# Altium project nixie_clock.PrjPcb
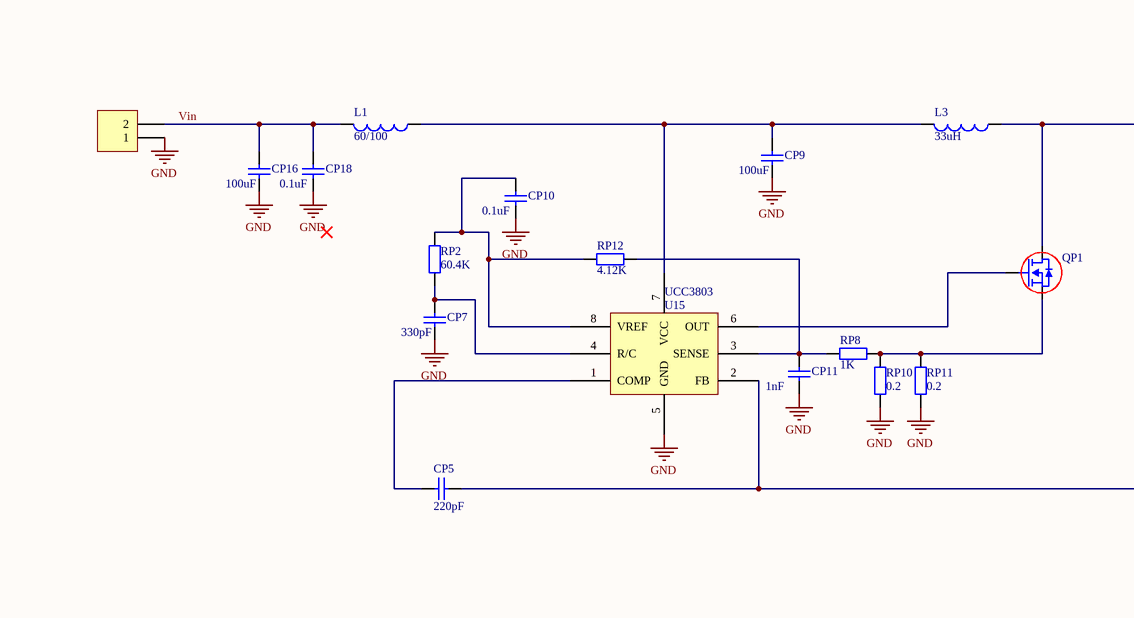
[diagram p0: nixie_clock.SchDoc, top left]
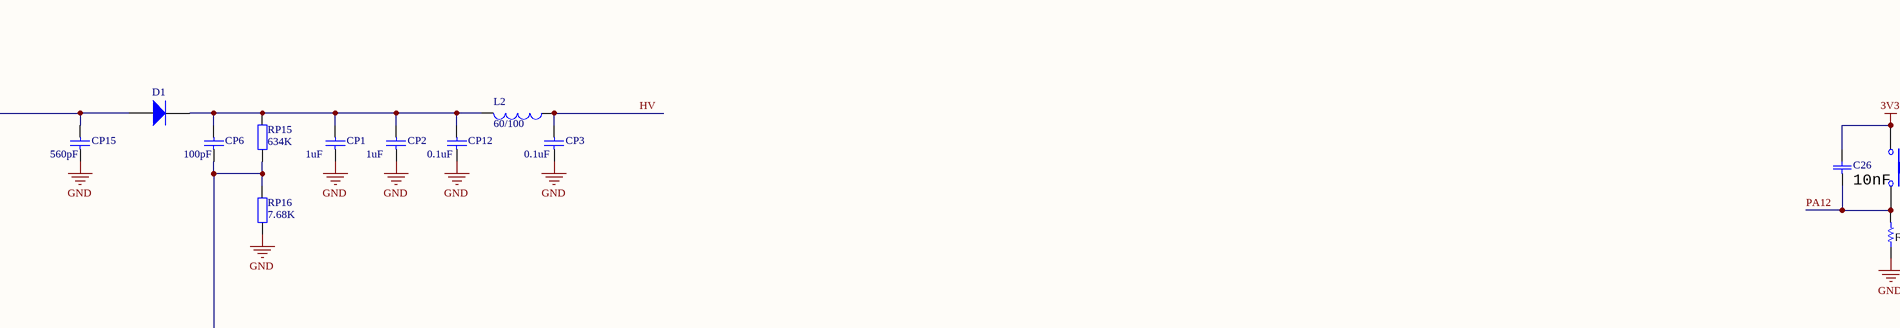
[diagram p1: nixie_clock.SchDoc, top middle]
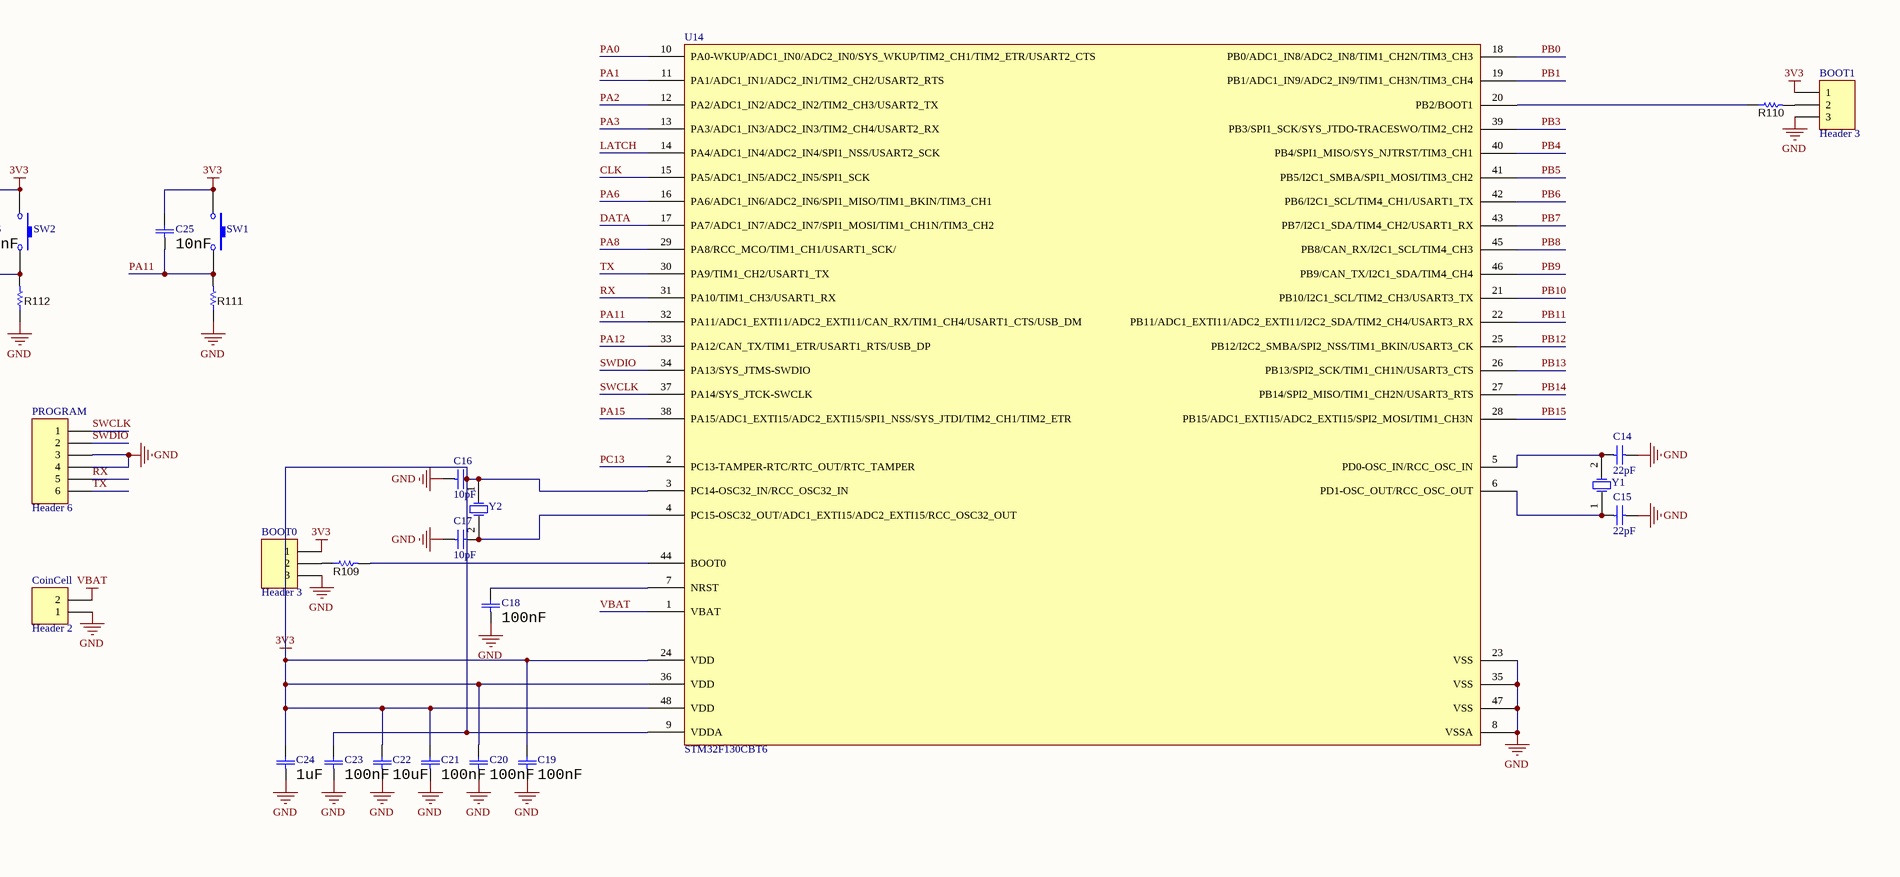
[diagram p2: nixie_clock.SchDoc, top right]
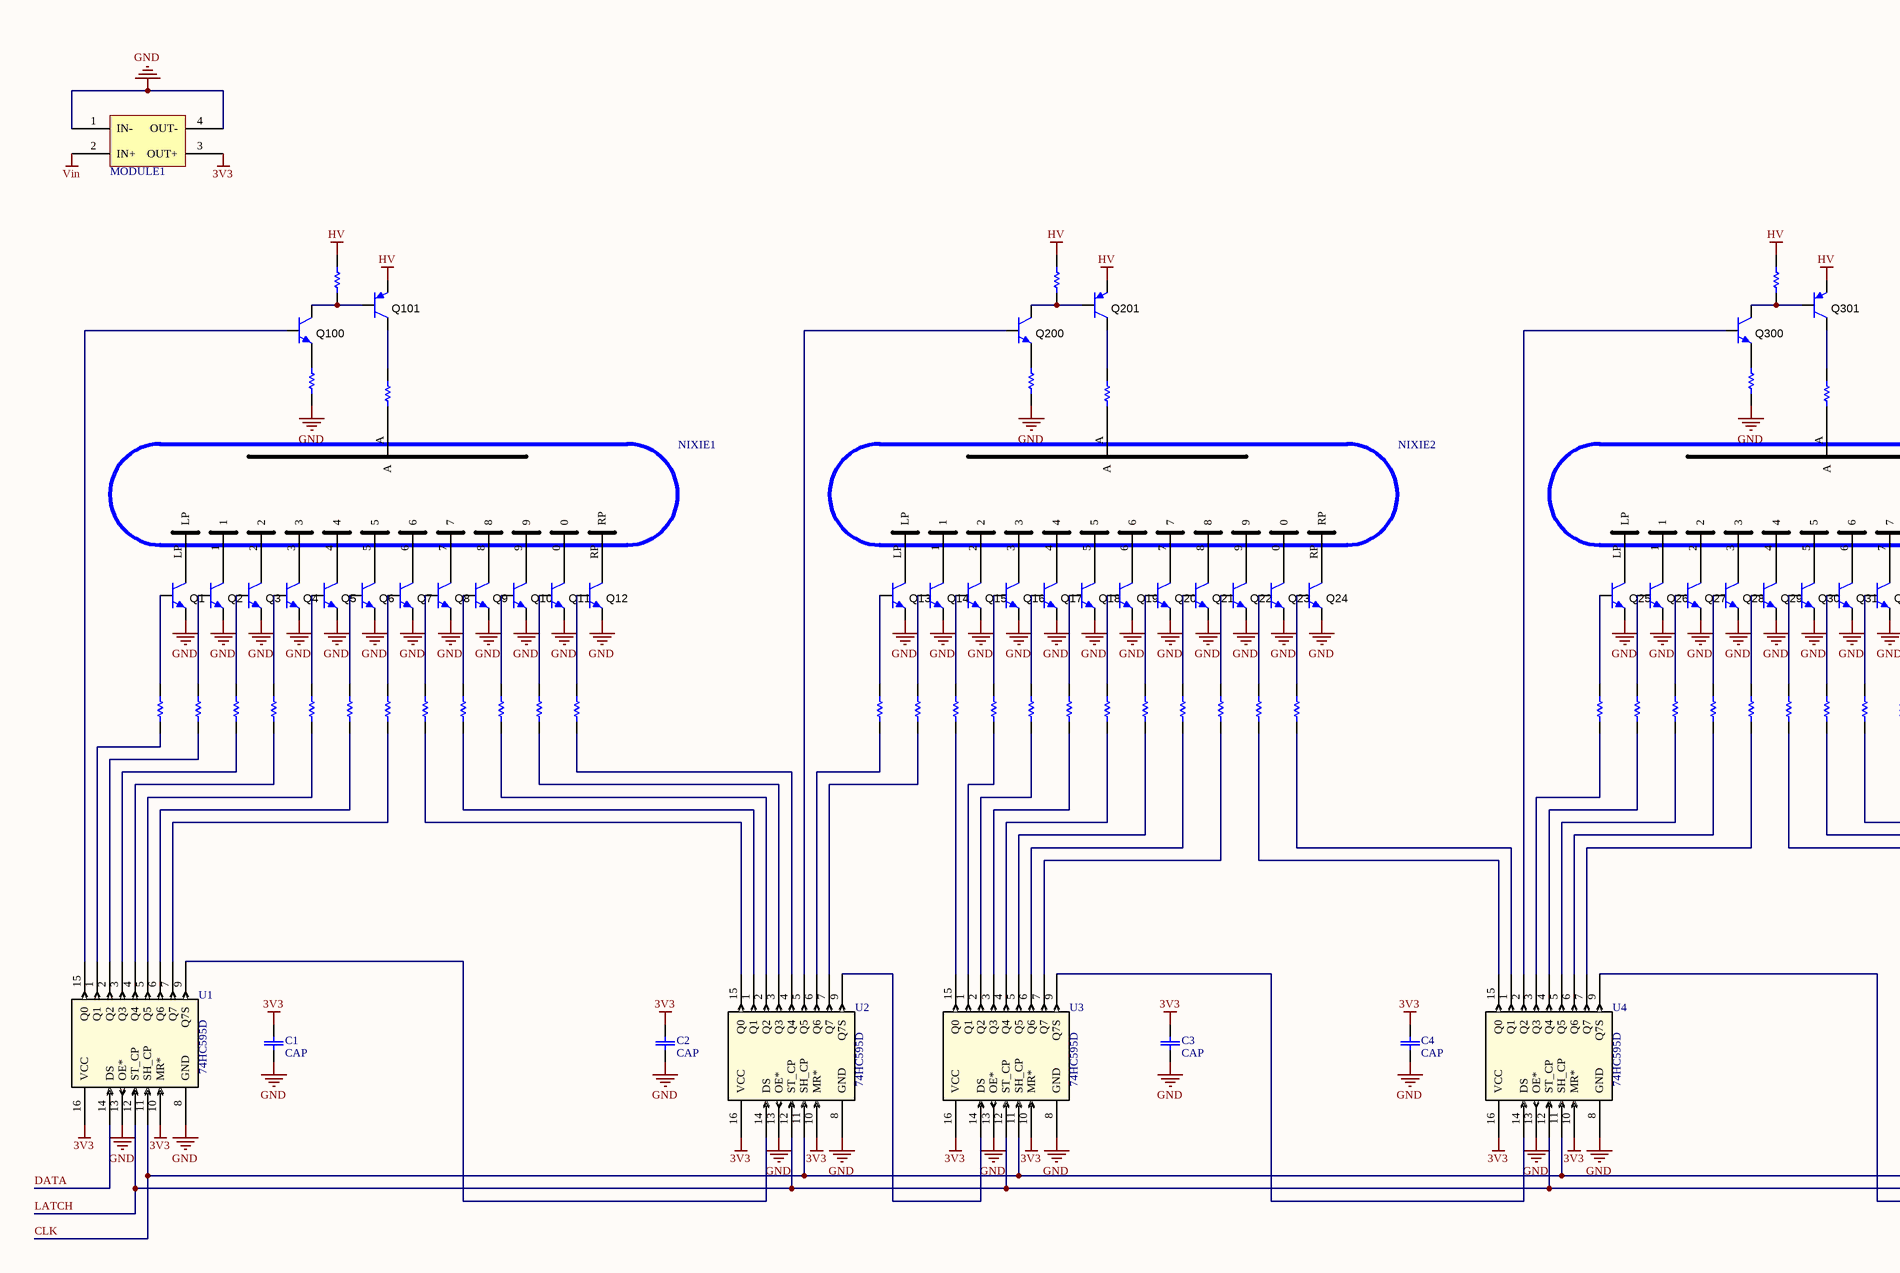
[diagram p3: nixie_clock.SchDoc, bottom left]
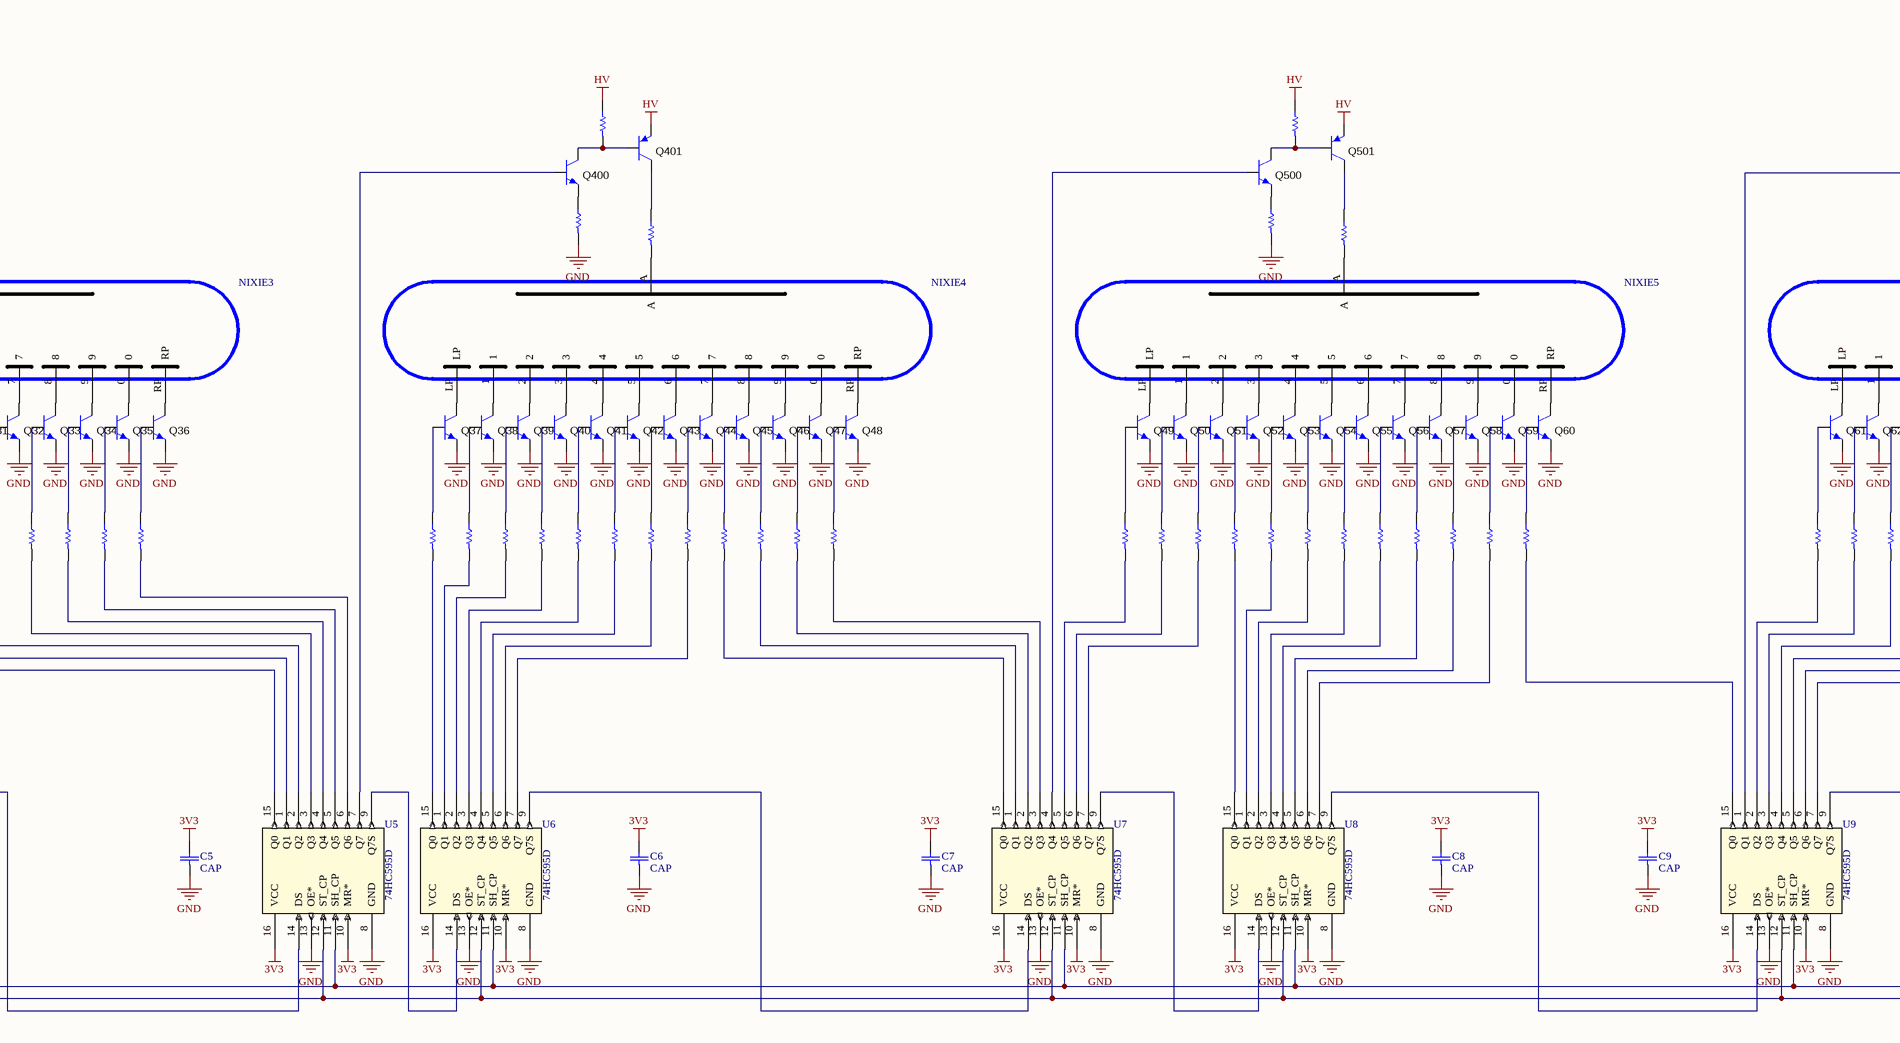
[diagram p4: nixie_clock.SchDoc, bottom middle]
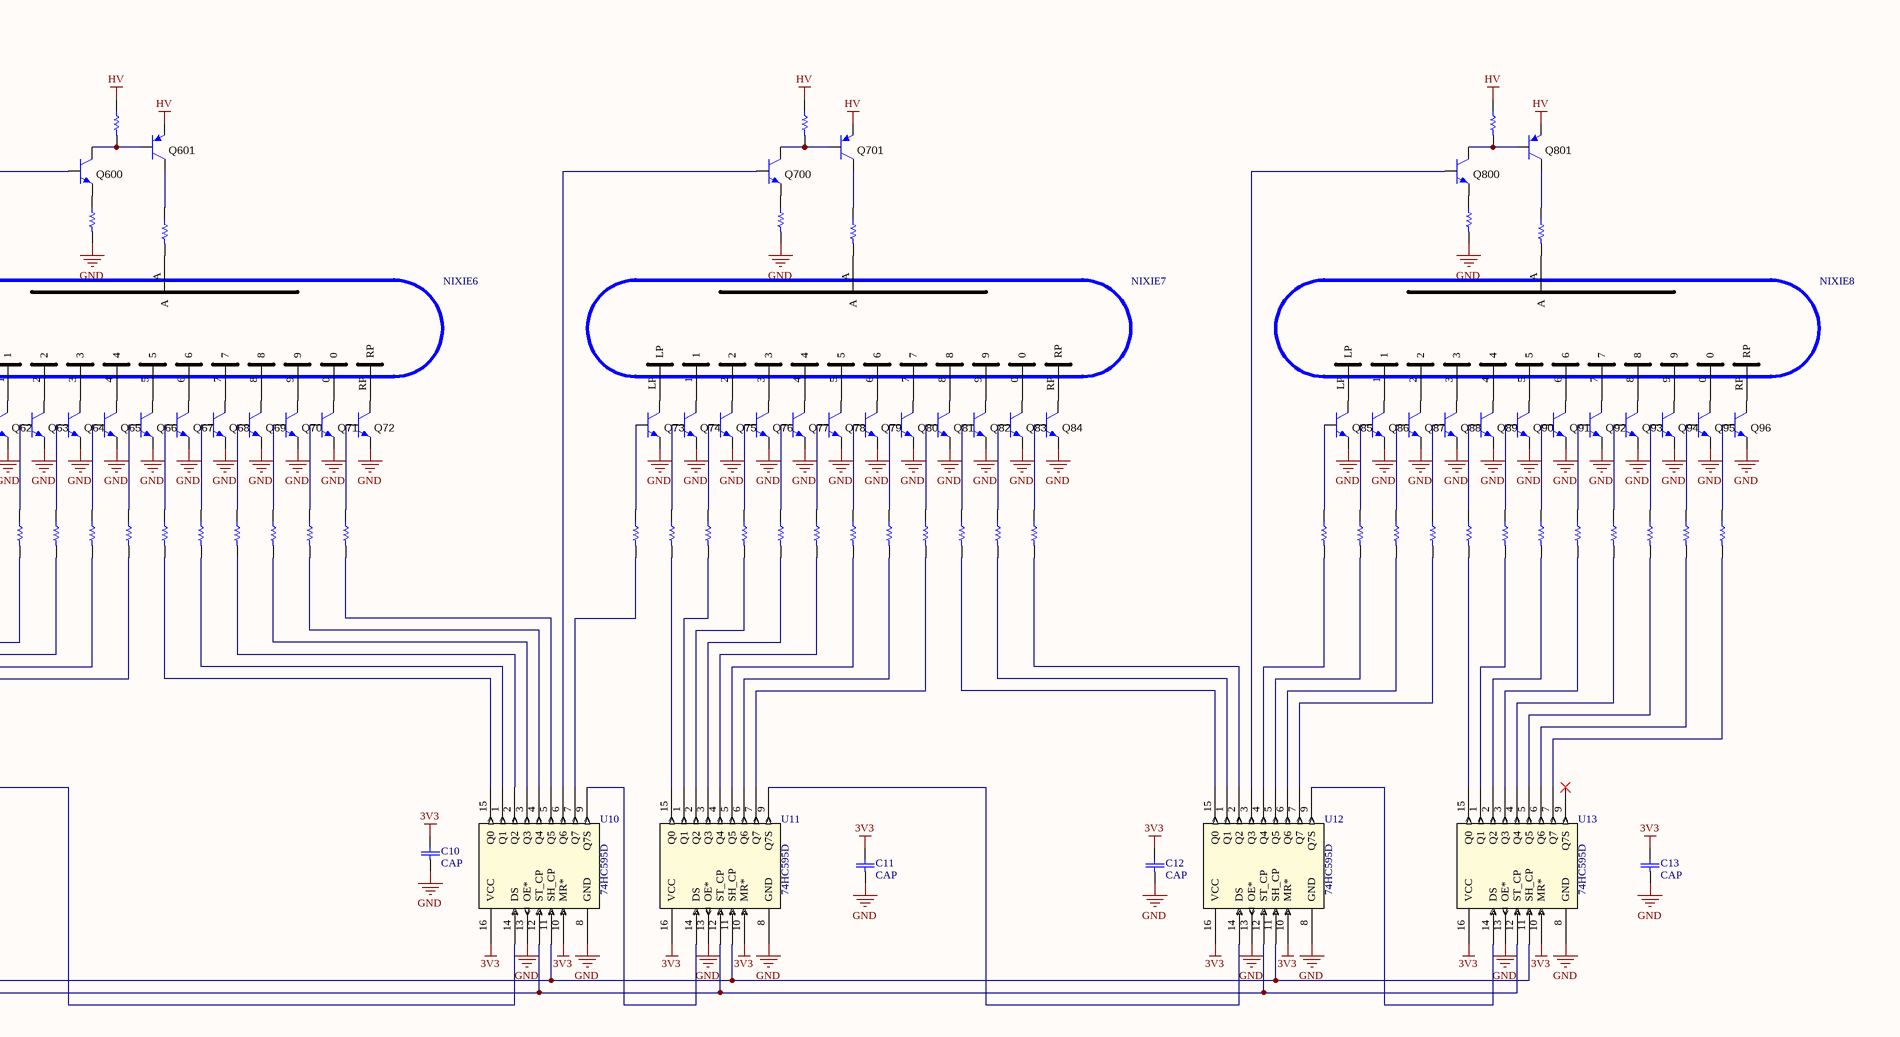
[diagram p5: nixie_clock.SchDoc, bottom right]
1 sheet, 320 parts. Net scope: global (net labels, ports and power ports of the same name join across sheets).
Board file: nixie_clock.PcbDoc

## Sheet nixie_clock.SchDoc
size 1270 x 635 mm; PageSetup: Record=PageOptions¦CenterHorizontal=True¦CenterVertical=True¦PrintScale=0.92¦XCorrection=1.00¦YCorrection=1.00¦PrintKind=0¦BorderSize=5000000¦LeftOffset=0¦BottomOffset=0¦Orientation=2¦PaperLength=11890¦PaperWidth=8410¦Scale=100¦PaperSource=7¦PrintQuality=600¦MediaType=1¦DitherType=10¦PrintScaleMode=1¦PaperKind=A0¦PaperIndex=119

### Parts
BOOT0  Header 3  [SMDJ]
BOOT1  Header 3  [smdj]
C1  CAP  [SMD[1206]]
C2  CAP  [SMD[1206]]
C3  CAP  [SMD[1206]]
C4  CAP  [SMD[1206]]
C5  CAP  [SMD[1206]]
C6  CAP  [SMD[1206]]
C7  CAP  [SMD[1206]]
C8  CAP  [SMD[1206]]
C9  CAP  [SMD[1206]]
C10  CAP  [SMD[1206]]
C11  CAP  [SMD[1206]]
C12  CAP  [SMD[1206]]
C13  CAP  [SMD[1206]]
C14  value 22pF  [SMD[1206]]  (hidden comment: Cap)
C15  value 22pF  [SMD[1206]]  (hidden comment: Cap)
C16  value 10pF  [SMD[0805]]  (hidden comment: Cap)
C17  value 10pF  [SMD[0805]]  (hidden comment: Cap)
C18  value 100nF  [SMD[1206]]  (hidden comment: CAP)
C19  value 100nF  [SMD[1206]]  (hidden comment: CAP)
C20  value 100nF  [SMD[1206]]  (hidden comment: CAP)
C21  value 100nF  [SMD[1206]]  (hidden comment: CAP)
C22  value 10uF  [SMD[1206]]  (hidden comment: CAP)
C23  value 100nF  [SMD[1206]]  (hidden comment: CAP)
C24  value 1uF  [SMD[1206]]  (hidden comment: CAP)
C25  value 10nF  [SMD[1206]]  (hidden comment: CAP)
C26  value 10nF  [SMD[1206]]  (hidden comment: CAP)
CoinCell  Header 2  [CoinCell[CR2032]]
CP1  value 1uF  [MKT27X10]  (hidden comment: Cap Semi)
CP2  value 1uF  [MKT27X10]  (hidden comment: Cap Semi)
CP3  value 0.1uF  [MKT18X6]  (hidden comment: Cap Semi)
CP5  value 220pF  [SMD[1206]]  (hidden comment: Cap Semi)
CP6  value 100pF  [CAP[SEC]]  (hidden comment: Cap Semi)
CP7  value 330pF  [SMD[1206]]  (hidden comment: Cap Semi)
CP9  value 100uF  [SMDCAP[D]]  (hidden comment: Cap Semi)
CP10  value 0.1uF  [SMDCAP[A]]  (hidden comment: Cap Semi)
CP11  value 1nF  [SMD[1206]]  (hidden comment: Cap Semi)
CP12  value 0.1uF  [MKT18X6]  (hidden comment: Cap Semi)
CP15  value 560pF  [CAP[SEC]]  (hidden comment: Cap Semi)
CP16  value 100uF  [SMDCAP[D]]  (hidden comment: Cap Semi)
CP18  value 0.1uF  [SMDCAP[A]]  (hidden comment: Cap Semi)
D1  Diode  [TO-220H-2PIN]  (value not drawn)
L1  value 60/100  [SMD[1206]]  (hidden comment: Inductor)
L2  value 60/100  [SMD[1206]]  (hidden comment: Inductor)
L3  value 33uH  [POWERINDUCTOR]  (hidden comment: Inductor)
MODULE1  TINY_STEPDOWN  [TINY_STEPDOWN]  (value not drawn)
NIXIE1  IN14_NIXIE_TUBE  [IN14_NIXIE_TUBE]  (value not drawn)
NIXIE2  IN14_NIXIE_TUBE  [IN14_NIXIE_TUBE]  (value not drawn)
NIXIE3  IN14_NIXIE_TUBE  [IN14_NIXIE_TUBE]  (value not drawn)
NIXIE4  IN14_NIXIE_TUBE  [IN14_NIXIE_TUBE]  (value not drawn)
NIXIE5  IN14_NIXIE_TUBE  [IN14_NIXIE_TUBE]  (value not drawn)
NIXIE6  IN14_NIXIE_TUBE  [IN14_NIXIE_TUBE]  (value not drawn)
NIXIE7  IN14_NIXIE_TUBE  [IN14_NIXIE_TUBE]  (value not drawn)
NIXIE8  IN14_NIXIE_TUBE  [IN14_NIXIE_TUBE]  (value not drawn)
P1  Header 2  [HDR1X2]  (value not drawn)
PROGRAM  Header 6  [H1X06F]
Q1  MMBTA42  [SOT23(TO236)]  (value not drawn)
Q2  MMBTA42  [SOT23(TO236)]  (value not drawn)
Q3  MMBTA42  [SOT23(TO236)]  (value not drawn)
Q4  MMBTA42  [SOT23(TO236)]  (value not drawn)
Q5  MMBTA42  [SOT23(TO236)]  (value not drawn)
Q6  MMBTA42  [SOT23(TO236)]  (value not drawn)
Q7  MMBTA42  [SOT23(TO236)]  (value not drawn)
Q8  MMBTA42  [SOT23(TO236)]  (value not drawn)
Q9  MMBTA42  [SOT23(TO236)]  (value not drawn)
Q10  MMBTA42  [SOT23(TO236)]  (value not drawn)
Q11  MMBTA42  [SOT23(TO236)]  (value not drawn)
Q12  MMBTA42  [SOT23(TO236)]  (value not drawn)
Q13  MMBTA42  [SOT23(TO236)]  (value not drawn)
Q14  MMBTA42  [SOT23(TO236)]  (value not drawn)
Q15  MMBTA42  [SOT23(TO236)]  (value not drawn)
Q16  MMBTA42  [SOT23(TO236)]  (value not drawn)
Q17  MMBTA42  [SOT23(TO236)]  (value not drawn)
Q18  MMBTA42  [SOT23(TO236)]  (value not drawn)
Q19  MMBTA42  [SOT23(TO236)]  (value not drawn)
Q20  MMBTA42  [SOT23(TO236)]  (value not drawn)
Q21  MMBTA42  [SOT23(TO236)]  (value not drawn)
Q22  MMBTA42  [SOT23(TO236)]  (value not drawn)
Q23  MMBTA42  [SOT23(TO236)]  (value not drawn)
Q24  MMBTA42  [SOT23(TO236)]  (value not drawn)
Q25  MMBTA42  [SOT23(TO236)]  (value not drawn)
Q26  MMBTA42  [SOT23(TO236)]  (value not drawn)
Q27  MMBTA42  [SOT23(TO236)]  (value not drawn)
Q28  MMBTA42  [SOT23(TO236)]  (value not drawn)
Q29  MMBTA42  [SOT23(TO236)]  (value not drawn)
Q30  MMBTA42  [SOT23(TO236)]  (value not drawn)
Q31  MMBTA42  [SOT23(TO236)]  (value not drawn)
Q32  MMBTA42  [SOT23(TO236)]  (value not drawn)
Q33  MMBTA42  [SOT23(TO236)]  (value not drawn)
Q34  MMBTA42  [SOT23(TO236)]  (value not drawn)
Q35  MMBTA42  [SOT23(TO236)]  (value not drawn)
Q36  MMBTA42  [SOT23(TO236)]  (value not drawn)
Q37  MMBTA42  [SOT23(TO236)]  (value not drawn)
Q38  MMBTA42  [SOT23(TO236)]  (value not drawn)
Q39  MMBTA42  [SOT23(TO236)]  (value not drawn)
Q40  MMBTA42  [SOT23(TO236)]  (value not drawn)
Q41  MMBTA42  [SOT23(TO236)]  (value not drawn)
Q42  MMBTA42  [SOT23(TO236)]  (value not drawn)
Q43  MMBTA42  [SOT23(TO236)]  (value not drawn)
Q44  MMBTA42  [SOT23(TO236)]  (value not drawn)
Q45  MMBTA42  [SOT23(TO236)]  (value not drawn)
Q46  MMBTA42  [SOT23(TO236)]  (value not drawn)
Q47  MMBTA42  [SOT23(TO236)]  (value not drawn)
Q48  MMBTA42  [SOT23(TO236)]  (value not drawn)
Q49  MMBTA42  [SOT23(TO236)]  (value not drawn)
Q50  MMBTA42  [SOT23(TO236)]  (value not drawn)
Q51  MMBTA42  [SOT23(TO236)]  (value not drawn)
Q52  MMBTA42  [SOT23(TO236)]  (value not drawn)
Q53  MMBTA42  [SOT23(TO236)]  (value not drawn)
Q54  MMBTA42  [SOT23(TO236)]  (value not drawn)
Q55  MMBTA42  [SOT23(TO236)]  (value not drawn)
Q56  MMBTA42  [SOT23(TO236)]  (value not drawn)
Q57  MMBTA42  [SOT23(TO236)]  (value not drawn)
Q58  MMBTA42  [SOT23(TO236)]  (value not drawn)
Q59  MMBTA42  [SOT23(TO236)]  (value not drawn)
Q60  MMBTA42  [SOT23(TO236)]  (value not drawn)
Q61  MMBTA42  [SOT23(TO236)]  (value not drawn)
Q62  MMBTA42  [SOT23(TO236)]  (value not drawn)
Q63  MMBTA42  [SOT23(TO236)]  (value not drawn)
Q64  MMBTA42  [SOT23(TO236)]  (value not drawn)
Q65  MMBTA42  [SOT23(TO236)]  (value not drawn)
Q66  MMBTA42  [SOT23(TO236)]  (value not drawn)
Q67  MMBTA42  [SOT23(TO236)]  (value not drawn)
Q68  MMBTA42  [SOT23(TO236)]  (value not drawn)
Q69  MMBTA42  [SOT23(TO236)]  (value not drawn)
Q70  MMBTA42  [SOT23(TO236)]  (value not drawn)
Q71  MMBTA42  [SOT23(TO236)]  (value not drawn)
Q72  MMBTA42  [SOT23(TO236)]  (value not drawn)
Q73  MMBTA42  [SOT23(TO236)]  (value not drawn)
Q74  MMBTA42  [SOT23(TO236)]  (value not drawn)
Q75  MMBTA42  [SOT23(TO236)]  (value not drawn)
Q76  MMBTA42  [SOT23(TO236)]  (value not drawn)
Q77  MMBTA42  [SOT23(TO236)]  (value not drawn)
Q78  MMBTA42  [SOT23(TO236)]  (value not drawn)
Q79  MMBTA42  [SOT23(TO236)]  (value not drawn)
Q80  MMBTA42  [SOT23(TO236)]  (value not drawn)
Q81  MMBTA42  [SOT23(TO236)]  (value not drawn)
Q82  MMBTA42  [SOT23(TO236)]  (value not drawn)
Q83  MMBTA42  [SOT23(TO236)]  (value not drawn)
Q84  MMBTA42  [SOT23(TO236)]  (value not drawn)
Q85  MMBTA42  [SOT23(TO236)]  (value not drawn)
Q86  MMBTA42  [SOT23(TO236)]  (value not drawn)
Q87  MMBTA42  [SOT23(TO236)]  (value not drawn)
Q88  MMBTA42  [SOT23(TO236)]  (value not drawn)
Q89  MMBTA42  [SOT23(TO236)]  (value not drawn)
Q90  MMBTA42  [SOT23(TO236)]  (value not drawn)
Q91  MMBTA42  [SOT23(TO236)]  (value not drawn)
Q92  MMBTA42  [SOT23(TO236)]  (value not drawn)
Q93  MMBTA42  [SOT23(TO236)]  (value not drawn)
Q94  MMBTA42  [SOT23(TO236)]  (value not drawn)
Q95  MMBTA42  [SOT23(TO236)]  (value not drawn)
Q96  MMBTA42  [SOT23(TO236)]  (value not drawn)
Q100  MMBTA42  [SOT23(TO236)]  (value not drawn)
Q101  MMBTA92  [SOT23(TO236)]  (value not drawn)
Q200  MMBTA42  [SOT23(TO236)]  (value not drawn)
Q201  MMBTA92  [SOT23(TO236)]  (value not drawn)
Q300  MMBTA42  [SOT23(TO236)]  (value not drawn)
Q301  MMBTA92  [SOT23(TO236)]  (value not drawn)
Q400  MMBTA42  [SOT23(TO236)]  (value not drawn)
Q401  MMBTA92  [SOT23(TO236)]  (value not drawn)
Q500  MMBTA42  [SOT23(TO236)]  (value not drawn)
Q501  MMBTA92  [SOT23(TO236)]  (value not drawn)
Q600  MMBTA42  [SOT23(TO236)]  (value not drawn)
Q601  MMBTA92  [SOT23(TO236)]  (value not drawn)
Q700  MMBTA42  [SOT23(TO236)]  (value not drawn)
Q701  MMBTA92  [SOT23(TO236)]  (value not drawn)
Q800  MMBTA42  [SOT23(TO236)]  (value not drawn)
Q801  MMBTA92  [SOT23(TO236)]  (value not drawn)
QP1  IRFB4229  [TO-220H]  (value not drawn)
R1  RES  [SMD[1206]]  (value not drawn)
R2  RES  [SMD[1206]]  (value not drawn)
R3  RES  [SMD[1206]]  (value not drawn)
R4  RES  [SMD[1206]]  (value not drawn)
R5  RES  [SMD[1206]]  (value not drawn)
R6  RES  [SMD[1206]]  (value not drawn)
R7  RES  [SMD[1206]]  (value not drawn)
R8  RES  [SMD[1206]]  (value not drawn)
R9  RES  [SMD[1206]]  (value not drawn)
R10  RES  [SMD[1206]]  (value not drawn)
R11  RES  [SMD[1206]]  (value not drawn)
R12  RES  [SMD[1206]]  (value not drawn)
R13  RES  [SMD[1206]]  (value not drawn)
R14  RES  [SMD[1206]]  (value not drawn)
R15  RES  [SMD[1206]]  (value not drawn)
R16  RES  [SMD[1206]]  (value not drawn)
R17  RES  [SMD[1206]]  (value not drawn)
R18  RES  [SMD[1206]]  (value not drawn)
R19  RES  [SMD[1206]]  (value not drawn)
R20  RES  [SMD[1206]]  (value not drawn)
R21  RES  [SMD[1206]]  (value not drawn)
R22  RES  [SMD[1206]]  (value not drawn)
R23  RES  [SMD[1206]]  (value not drawn)
R24  RES  [SMD[1206]]  (value not drawn)
R25  RES  [SMD[1206]]  (value not drawn)
R26  RES  [SMD[1206]]  (value not drawn)
R27  RES  [SMD[1206]]  (value not drawn)
R28  RES  [SMD[1206]]  (value not drawn)
R29  RES  [SMD[1206]]  (value not drawn)
R30  RES  [SMD[1206]]  (value not drawn)
R31  RES  [SMD[1206]]  (value not drawn)
R32  RES  [SMD[1206]]  (value not drawn)
R33  RES  [SMD[1206]]  (value not drawn)
R34  RES  [SMD[1206]]  (value not drawn)
R35  RES  [SMD[1206]]  (value not drawn)
R36  RES  [SMD[1206]]  (value not drawn)
R37  RES  [SMD[1206]]  (value not drawn)
R38  RES  [SMD[1206]]  (value not drawn)
R39  RES  [SMD[1206]]  (value not drawn)
R40  RES  [SMD[1206]]  (value not drawn)
R41  RES  [SMD[1206]]  (value not drawn)
R42  RES  [SMD[1206]]  (value not drawn)
R43  RES  [SMD[1206]]  (value not drawn)
R44  RES  [SMD[1206]]  (value not drawn)
R45  RES  [SMD[1206]]  (value not drawn)
R46  RES  [SMD[1206]]  (value not drawn)
R47  RES  [SMD[1206]]  (value not drawn)
R48  RES  [SMD[1206]]  (value not drawn)
R49  RES  [SMD[1206]]  (value not drawn)
R50  RES  [SMD[1206]]  (value not drawn)
R51  RES  [SMD[1206]]  (value not drawn)
R52  RES  [SMD[1206]]  (value not drawn)
R53  RES  [SMD[1206]]  (value not drawn)
R54  RES  [SMD[1206]]  (value not drawn)
R55  RES  [SMD[1206]]  (value not drawn)
R56  RES  [SMD[1206]]  (value not drawn)
R57  RES  [SMD[1206]]  (value not drawn)
R58  RES  [SMD[1206]]  (value not drawn)
R59  RES  [SMD[1206]]  (value not drawn)
R60  RES  [SMD[1206]]  (value not drawn)
R61  RES  [SMD[1206]]  (value not drawn)
R62  RES  [SMD[1206]]  (value not drawn)
R63  RES  [SMD[1206]]  (value not drawn)
R64  RES  [SMD[1206]]  (value not drawn)
R65  RES  [SMD[1206]]  (value not drawn)
R66  RES  [SMD[1206]]  (value not drawn)
R67  RES  [SMD[1206]]  (value not drawn)
R68  RES  [SMD[1206]]  (value not drawn)
R69  RES  [SMD[1206]]  (value not drawn)
R70  RES  [SMD[1206]]  (value not drawn)
R71  RES  [SMD[1206]]  (value not drawn)
R72  RES  [SMD[1206]]  (value not drawn)
R73  RES  [SMD[1206]]  (value not drawn)
R74  RES  [SMD[1206]]  (value not drawn)
R75  RES  [SMD[1206]]  (value not drawn)
R76  RES  [SMD[1206]]  (value not drawn)
R77  RES  [SMD[1206]]  (value not drawn)
R78  RES  [SMD[1206]]  (value not drawn)
R79  RES  [SMD[1206]]  (value not drawn)
R80  RES  [SMD[1206]]  (value not drawn)
R81  RES  [SMD[1206]]  (value not drawn)
R82  RES  [SMD[1206]]  (value not drawn)
R83  RES  [SMD[1206]]  (value not drawn)
R84  RES  [SMD[1206]]  (value not drawn)
R85  RES  [SMD[1206]]  (value not drawn)
R86  RES  [SMD[1206]]  (value not drawn)
R87  RES  [SMD[1206]]  (value not drawn)
R88  RES  [SMD[1206]]  (value not drawn)
R89  RES  [SMD[1206]]  (value not drawn)
R90  RES  [SMD[1206]]  (value not drawn)
R91  RES  [SMD[1206]]  (value not drawn)
R92  RES  [SMD[1206]]  (value not drawn)
R93  RES  [SMD[1206]]  (value not drawn)
R94  RES  [SMD[1206]]  (value not drawn)
R95  RES  [SMD[1206]]  (value not drawn)
R96  RES  [SMD[1206]]  (value not drawn)
R100  RES  [SMD[1206]]  (value not drawn)
R101  RES  [SMD[1206]]  (value not drawn)
R102  RES  [SMD[1206]]  (value not drawn)
R109  RES  [SMD[1206]]  (value not drawn)
R110  RES  [SMD[1206]]  (value not drawn)
R111  RES  [SMD[1206]]  (value not drawn)
R112  RES  [SMD[1206]]  (value not drawn)
R200  RES  [SMD[1206]]  (value not drawn)
R201  RES  [SMD[1206]]  (value not drawn)
R202  RES  [SMD[1206]]  (value not drawn)
R300  RES  [SMD[1206]]  (value not drawn)
R301  RES  [SMD[1206]]  (value not drawn)
R302  RES  [SMD[1206]]  (value not drawn)
R400  RES  [SMD[1206]]  (value not drawn)
R401  RES  [SMD[1206]]  (value not drawn)
R402  RES  [SMD[1206]]  (value not drawn)
R500  RES  [SMD[1206]]  (value not drawn)
R501  RES  [SMD[1206]]  (value not drawn)
R502  RES  [SMD[1206]]  (value not drawn)
R600  RES  [SMD[1206]]  (value not drawn)
R601  RES  [SMD[1206]]  (value not drawn)
R602  RES  [SMD[1206]]  (value not drawn)
R700  RES  [SMD[1206]]  (value not drawn)
R701  RES  [SMD[1206]]  (value not drawn)
R702  RES  [SMD[1206]]  (value not drawn)
R800  RES  [SMD[1206]]  (value not drawn)
R801  RES  [SMD[1206]]  (value not drawn)
R802  RES  [SMD[1206]]  (value not drawn)
RP2  value 60.4K  [SMD[1206]]  (hidden comment: Res2)
RP8  value 1K  [SMD[1206]]  (hidden comment: Res2)
RP10  value 0.2  [SMD[1206]]  (hidden comment: Res2)
RP11  value 0.2  [SMD[1206]]  (hidden comment: Res2)
RP12  value 4.12K  [SMD[1206]]  (hidden comment: Res2)
RP15  value 634K  [SMD[1206]]  (hidden comment: Res2)
RP16  value 7.68K  [SMD[1206]]  (hidden comment: Res2)
SW1  SW-PB  [PUSHBUTTON]  (value not drawn)
SW2  SW-PB  [PUSHBUTTON]  (value not drawn)
U1  74HC595D  [SOIC16]
U2  74HC595D  [SOIC16]
U3  74HC595D  [SOIC16]
U4  74HC595D  [SOIC16]
U5  74HC595D  [SOIC16]
U6  74HC595D  [SOIC16]
U7  74HC595D  [SOIC16]
U8  74HC595D  [SOIC16]
U9  74HC595D  [SOIC16]
U10  74HC595D  [SOIC16]
U11  74HC595D  [SOIC16]
U12  74HC595D  [SOIC16]
U13  74HC595D  [SOIC16]
U14  STM32F130CBT6  [LQFP48]
U15  UCC3803  [SOIC8]
Y1  XTAL  [CRYSTALL]  (value not drawn)
Y2  XTAL  [MC406[32.768KHZ]]  (value not drawn)

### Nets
3V3: BOOT0.1 BOOT1.1 C1.2 C2.2 C3.2 C4.2 C5.2 C6.2 C7.2 C8.2 C9.2 C10.2 C11.2 C12.2 C13.2 C16.2 C19.2 C20.2 C21.2 C22.2 C23.2 C24.2 C25.2 C26.2 MODULE1.3(OUT+) SW1.1 SW2.1 U1.10(MR*) U1.16(VCC) U2.10(MR*) U2.16(VCC) U3.10(MR*) U3.16(VCC) U4.10(MR*) U4.16(VCC) U5.10(MR*) U5.16(VCC) U6.10(MR*) U6.16(VCC) U7.10(MR*) U7.16(VCC) U8.10(MR*) U8.16(VCC) U9.10(MR*) U9.16(VCC) U10.10(MR*) U10.16(VCC) U11.10(MR*) U11.16(VCC) U12.10(MR*) U12.16(VCC) U13.10(MR*) U13.16(VCC) U14.3(PC14-OSC32_IN/RCC_OSC32_IN) U14.9(VDDA) U14.24(VDD) U14.36(VDD) U14.48(VDD) Y2.1(OSC1)
GND: BOOT0.3 BOOT1.3 C1.1 C2.1 C3.1 C4.1 C5.1 C6.1 C7.1 C8.1 C9.1 C10.1 C11.1 C12.1 C13.1 C14.1 C15.1 C16.1 C17.1 C18.1 C19.1 C20.1 C21.1 C22.1 C23.1 C24.1 CoinCell.1 CP1.2 CP2.2 CP3.2 CP7.2 CP9.2 CP10.2 CP11.2 CP12.2 CP15.2 CP16.2 CP18.2 MODULE1.1(IN-) MODULE1.4(OUT-) P1.2(1) PROGRAM.3 PROGRAM.4 Q1.2(E) Q2.2(E) Q3.2(E) Q4.2(E) Q5.2(E) Q6.2(E) Q7.2(E) Q8.2(E) Q9.2(E) Q10.2(E) Q11.2(E) Q12.2(E) Q13.2(E) Q14.2(E) Q15.2(E) Q16.2(E) Q17.2(E) Q18.2(E) Q19.2(E) Q20.2(E) Q21.2(E) Q22.2(E) Q23.2(E) Q24.2(E) Q25.2(E) Q26.2(E) Q27.2(E) Q28.2(E) Q29.2(E) Q30.2(E) Q31.2(E) Q32.2(E) Q33.2(E) Q34.2(E) Q35.2(E) Q36.2(E) Q37.2(E) Q38.2(E) Q39.2(E) Q40.2(E) Q41.2(E) Q42.2(E) Q43.2(E) Q44.2(E) Q45.2(E) Q46.2(E) Q47.2(E) Q48.2(E) Q49.2(E) Q50.2(E) Q51.2(E) Q52.2(E) Q53.2(E) Q54.2(E) Q55.2(E) Q56.2(E) Q57.2(E) Q58.2(E) Q59.2(E) Q60.2(E) Q61.2(E) Q62.2(E) Q63.2(E) Q64.2(E) Q65.2(E) Q66.2(E) Q67.2(E) Q68.2(E) Q69.2(E) Q70.2(E) Q71.2(E) Q72.2(E) Q73.2(E) Q74.2(E) Q75.2(E) Q76.2(E) Q77.2(E) Q78.2(E) Q79.2(E) Q80.2(E) Q81.2(E) Q82.2(E) Q83.2(E) Q84.2(E) Q85.2(E) Q86.2(E) Q87.2(E) Q88.2(E) Q89.2(E) Q90.2(E) Q91.2(E) Q92.2(E) Q93.2(E) Q94.2(E) Q95.2(E) Q96.2(E) R100.2 R111.1 R112.1 R200.2 R300.2 R400.2 R500.2 R600.2 R700.2 R800.2 RP10.2 RP11.2 RP16.2 U1.8(GND) U1.13(OE*) U2.8(GND) U2.13(OE*) U3.8(GND) U3.13(OE*) U4.8(GND) U4.13(OE*) U5.8(GND) U5.13(OE*) U6.8(GND) U6.13(OE*) U7.8(GND) U7.13(OE*) U8.8(GND) U8.13(OE*) U9.8(GND) U9.13(OE*) U10.8(GND) U10.13(OE*) U11.8(GND) U11.13(OE*) U12.8(GND) U12.13(OE*) U13.8(GND) U13.13(OE*) U14.8(VSSA) U14.23(VSS) U14.35(VSS) U14.47(VSS) U15.5(GND)
HV: CP3.1 L2.1 Q101.2(E) Q201.2(E) Q301.2(E) Q401.2(E) Q501.2(E) Q601.2(E) Q701.2(E) Q801.2(E) R102.1 R202.1 R302.1 R402.1 R502.1 R602.1 R702.1 R802.1
VBAT: CoinCell.2 U14.1(VBAT)
Vin: CP16.1 CP18.1 L1.2 MODULE1.2(IN+) P1.1(2)
CLK: U1.11(SH_CP) U2.11(SH_CP) U3.11(SH_CP) U4.11(SH_CP) U5.11(SH_CP) U6.11(SH_CP) U7.11(SH_CP) U8.11(SH_CP) U9.11(SH_CP) U10.11(SH_CP) U11.11(SH_CP) U12.11(SH_CP) U13.11(SH_CP) U14.15(PA5/ADC1_IN5/ADC2_IN5/SPI1_SCK)
DATA: U1.14(DS) U14.17(PA7/ADC1_IN7/ADC2_IN7/SPI1_MOSI/TIM1_CH1N/TIM3_CH2)
LATCH: U1.12(ST_CP) U2.12(ST_CP) U3.12(ST_CP) U4.12(ST_CP) U5.12(ST_CP) U6.12(ST_CP) U7.12(ST_CP) U8.12(ST_CP) U9.12(ST_CP) U10.12(ST_CP) U11.12(ST_CP) U12.12(ST_CP) U13.12(ST_CP) U14.14(PA4/ADC1_IN4/ADC2_IN4/SPI1_NSS/USART2_SCK)
PA0: U14.10(PA0-WKUP/ADC1_IN0/ADC2_IN0/SYS_WKUP/TIM2_CH1/TIM2_ETR/USART2_CTS)
PA1: U14.11(PA1/ADC1_IN1/ADC2_IN1/TIM2_CH2/USART2_RTS)
PA2: U14.12(PA2/ADC1_IN2/ADC2_IN2/TIM2_CH3/USART2_TX)
PA3: U14.13(PA3/ADC1_IN3/ADC2_IN3/TIM2_CH4/USART2_RX)
PA6: U14.16(PA6/ADC1_IN6/ADC2_IN6/SPI1_MISO/TIM1_BKIN/TIM3_CH1)
PA8: U14.29(PA8/RCC_MCO/TIM1_CH1/USART1_SCK/)
PA11: C25.1 R111.2 SW1.2 U14.32(PA11/ADC1_EXTI11/ADC2_EXTI11/CAN_RX/TIM1_CH4/USART1_CTS/USB_DM)
PA12: C26.1 R112.2 SW2.2 U14.33(PA12/CAN_TX/TIM1_ETR/USART1_RTS/USB_DP)
PA15: U14.38(PA15/ADC1_EXTI15/ADC2_EXTI15/SPI1_NSS/SYS_JTDI/TIM2_CH1/TIM2_ETR)
PB0: U14.18(PB0/ADC1_IN8/ADC2_IN8/TIM1_CH2N/TIM3_CH3)
PB1: U14.19(PB1/ADC1_IN9/ADC2_IN9/TIM1_CH3N/TIM3_CH4)
PB3: U14.39(PB3/SPI1_SCK/SYS_JTDO-TRACESWO/TIM2_CH2)
PB4: U14.40(PB4/SPI1_MISO/SYS_NJTRST/TIM3_CH1)
PB5: U14.41(PB5/I2C1_SMBA/SPI1_MOSI/TIM3_CH2)
PB6: U14.42(PB6/I2C1_SCL/TIM4_CH1/USART1_TX)
PB7: U14.43(PB7/I2C1_SDA/TIM4_CH2/USART1_RX)
PB8: U14.45(PB8/CAN_RX/I2C1_SCL/TIM4_CH3)
PB9: U14.46(PB9/CAN_TX/I2C1_SDA/TIM4_CH4)
PB10: U14.21(PB10/I2C1_SCL/TIM2_CH3/USART3_TX)
PB11: U14.22(PB11/ADC1_EXTI11/ADC2_EXTI11/I2C2_SDA/TIM2_CH4/USART3_RX)
PB12: U14.25(PB12/I2C2_SMBA/SPI2_NSS/TIM1_BKIN/USART3_CK)
PB13: U14.26(PB13/SPI2_SCK/TIM1_CH1N/USART3_CTS)
PB14: U14.27(PB14/SPI2_MISO/TIM1_CH2N/USART3_RTS)
PB15: U14.28(PB15/ADC1_EXTI15/ADC2_EXTI15/SPI2_MOSI/TIM1_CH3N)
PC13: U14.2(PC13-TAMPER-RTC/RTC_OUT/RTC_TAMPER)
RX: PROGRAM.5 U14.31(PA10/TIM1_CH3/USART1_RX)
SWCLK: PROGRAM.1 U14.37(PA14/SYS_JTCK-SWCLK)
SWDIO: PROGRAM.2 U14.34(PA13/SYS_JTMS-SWDIO)
TX: PROGRAM.6 U14.30(PA9/TIM1_CH2/USART1_TX)
NetBOOT0_2: BOOT0.2 R109.1
NetBOOT1_2: BOOT1.2 R110.2
NetC14_2: C14.2 U14.5(PD0-OSC_IN/RCC_OSC_IN) Y1.2(OSC2)
NetC15_2: C15.2 U14.6(PD1-OSC_OUT/RCC_OSC_OUT) Y1.1(OSC1)
NetC17_2: C17.2 U14.4(PC15-OSC32_OUT/ADC1_EXTI15/ADC2_EXTI15/RCC_OSC32_OUT) Y2.2(OSC2)
NetC18_2: C18.2 U14.7(NRST)
NetCP1_1: CP1.1 CP2.1 CP6.1 CP12.1 D1.2(K) L2.2 RP15.1
NetCP5_1: CP5.1 U15.1(COMP)
NetCP5_2: CP5.2 CP6.2 RP15.2 RP16.1 U15.2(FB)
NetCP7_1: CP7.1 RP2.2 U15.4(R/C)
NetCP9_1: CP9.1 L1.1 L3.2 U15.7(VCC)
NetCP10_1: CP10.1 RP2.1 RP12.1 U15.8(VREF)
NetCP11_1: CP11.1 RP8.1 RP12.2 U15.3(SENSE)
NetCP15_1: CP15.1 D1.1(A) L3.1 QP1.2(D)
NetNIXIE1_0: NIXIE1.0 Q11.3(C)
NetNIXIE1_1: NIXIE1.1 Q2.3(C)
NetNIXIE1_2: NIXIE1.2 Q3.3(C)
NetNIXIE1_3: NIXIE1.3 Q4.3(C)
NetNIXIE1_4: NIXIE1.4 Q5.3(C)
NetNIXIE1_5: NIXIE1.5 Q6.3(C)
NetNIXIE1_6: NIXIE1.6 Q7.3(C)
NetNIXIE1_7: NIXIE1.7 Q8.3(C)
NetNIXIE1_8: NIXIE1.8 Q9.3(C)
NetNIXIE1_9: NIXIE1.9 Q10.3(C)
NetNIXIE1_A: NIXIE1.A R101.2
NetNIXIE1_LP: NIXIE1.LP Q1.3(C)
NetNIXIE1_RP: NIXIE1.RP Q12.3(C)
NetNIXIE2_0: NIXIE2.0 Q23.3(C)
NetNIXIE2_1: NIXIE2.1 Q14.3(C)
NetNIXIE2_2: NIXIE2.2 Q15.3(C)
NetNIXIE2_3: NIXIE2.3 Q16.3(C)
NetNIXIE2_4: NIXIE2.4 Q17.3(C)
NetNIXIE2_5: NIXIE2.5 Q18.3(C)
NetNIXIE2_6: NIXIE2.6 Q19.3(C)
NetNIXIE2_7: NIXIE2.7 Q20.3(C)
NetNIXIE2_8: NIXIE2.8 Q21.3(C)
NetNIXIE2_9: NIXIE2.9 Q22.3(C)
NetNIXIE2_A: NIXIE2.A R201.2
NetNIXIE2_LP: NIXIE2.LP Q13.3(C)
NetNIXIE2_RP: NIXIE2.RP Q24.3(C)
NetNIXIE3_0: NIXIE3.0 Q35.3(C)
NetNIXIE3_1: NIXIE3.1 Q26.3(C)
NetNIXIE3_2: NIXIE3.2 Q27.3(C)
NetNIXIE3_3: NIXIE3.3 Q28.3(C)
NetNIXIE3_4: NIXIE3.4 Q29.3(C)
NetNIXIE3_5: NIXIE3.5 Q30.3(C)
NetNIXIE3_6: NIXIE3.6 Q31.3(C)
NetNIXIE3_7: NIXIE3.7 Q32.3(C)
NetNIXIE3_8: NIXIE3.8 Q33.3(C)
NetNIXIE3_9: NIXIE3.9 Q34.3(C)
NetNIXIE3_A: NIXIE3.A R301.2
NetNIXIE3_LP: NIXIE3.LP Q25.3(C)
NetNIXIE3_RP: NIXIE3.RP Q36.3(C)
NetNIXIE4_0: NIXIE4.0 Q47.3(C)
NetNIXIE4_1: NIXIE4.1 Q38.3(C)
NetNIXIE4_2: NIXIE4.2 Q39.3(C)
NetNIXIE4_3: NIXIE4.3 Q40.3(C)
NetNIXIE4_4: NIXIE4.4 Q41.3(C)
NetNIXIE4_5: NIXIE4.5 Q42.3(C)
NetNIXIE4_6: NIXIE4.6 Q43.3(C)
NetNIXIE4_7: NIXIE4.7 Q44.3(C)
NetNIXIE4_8: NIXIE4.8 Q45.3(C)
NetNIXIE4_9: NIXIE4.9 Q46.3(C)
NetNIXIE4_A: NIXIE4.A R401.2
NetNIXIE4_LP: NIXIE4.LP Q37.3(C)
NetNIXIE4_RP: NIXIE4.RP Q48.3(C)
NetNIXIE5_0: NIXIE5.0 Q59.3(C)
NetNIXIE5_1: NIXIE5.1 Q50.3(C)
NetNIXIE5_2: NIXIE5.2 Q51.3(C)
NetNIXIE5_3: NIXIE5.3 Q52.3(C)
NetNIXIE5_4: NIXIE5.4 Q53.3(C)
NetNIXIE5_5: NIXIE5.5 Q54.3(C)
NetNIXIE5_6: NIXIE5.6 Q55.3(C)
NetNIXIE5_7: NIXIE5.7 Q56.3(C)
NetNIXIE5_8: NIXIE5.8 Q57.3(C)
NetNIXIE5_9: NIXIE5.9 Q58.3(C)
NetNIXIE5_A: NIXIE5.A R501.2
NetNIXIE5_LP: NIXIE5.LP Q49.3(C)
NetNIXIE5_RP: NIXIE5.RP Q60.3(C)
NetNIXIE6_0: NIXIE6.0 Q71.3(C)
NetNIXIE6_1: NIXIE6.1 Q62.3(C)
NetNIXIE6_2: NIXIE6.2 Q63.3(C)
NetNIXIE6_3: NIXIE6.3 Q64.3(C)
NetNIXIE6_4: NIXIE6.4 Q65.3(C)
NetNIXIE6_5: NIXIE6.5 Q66.3(C)
NetNIXIE6_6: NIXIE6.6 Q67.3(C)
NetNIXIE6_7: NIXIE6.7 Q68.3(C)
NetNIXIE6_8: NIXIE6.8 Q69.3(C)
NetNIXIE6_9: NIXIE6.9 Q70.3(C)
NetNIXIE6_A: NIXIE6.A R601.2
NetNIXIE6_LP: NIXIE6.LP Q61.3(C)
NetNIXIE6_RP: NIXIE6.RP Q72.3(C)
NetNIXIE7_0: NIXIE7.0 Q83.3(C)
NetNIXIE7_1: NIXIE7.1 Q74.3(C)
NetNIXIE7_2: NIXIE7.2 Q75.3(C)
NetNIXIE7_3: NIXIE7.3 Q76.3(C)
NetNIXIE7_4: NIXIE7.4 Q77.3(C)
NetNIXIE7_5: NIXIE7.5 Q78.3(C)
NetNIXIE7_6: NIXIE7.6 Q79.3(C)
NetNIXIE7_7: NIXIE7.7 Q80.3(C)
NetNIXIE7_8: NIXIE7.8 Q81.3(C)
NetNIXIE7_9: NIXIE7.9 Q82.3(C)
NetNIXIE7_A: NIXIE7.A R701.2
NetNIXIE7_LP: NIXIE7.LP Q73.3(C)
NetNIXIE7_RP: NIXIE7.RP Q84.3(C)
NetNIXIE8_0: NIXIE8.0 Q95.3(C)
NetNIXIE8_1: NIXIE8.1 Q86.3(C)
NetNIXIE8_2: NIXIE8.2 Q87.3(C)
NetNIXIE8_3: NIXIE8.3 Q88.3(C)
NetNIXIE8_4: NIXIE8.4 Q89.3(C)
NetNIXIE8_5: NIXIE8.5 Q90.3(C)
NetNIXIE8_6: NIXIE8.6 Q91.3(C)
NetNIXIE8_7: NIXIE8.7 Q92.3(C)
NetNIXIE8_8: NIXIE8.8 Q93.3(C)
NetNIXIE8_9: NIXIE8.9 Q94.3(C)
NetNIXIE8_A: NIXIE8.A R801.2
NetNIXIE8_LP: NIXIE8.LP Q85.3(C)
NetNIXIE8_RP: NIXIE8.RP Q96.3(C)
NetQ1_1: Q1.1(B) R1.1
NetQ2_1: Q2.1(B) R2.1
NetQ3_1: Q3.1(B) R3.1
NetQ4_1: Q4.1(B) R4.1
NetQ5_1: Q5.1(B) R5.1
NetQ6_1: Q6.1(B) R6.1
NetQ7_1: Q7.1(B) R7.1
NetQ8_1: Q8.1(B) R8.1
NetQ9_1: Q9.1(B) R9.1
NetQ10_1: Q10.1(B) R10.1
NetQ11_1: Q11.1(B) R11.1
NetQ12_1: Q12.1(B) R12.1
NetQ13_1: Q13.1(B) R13.1
NetQ14_1: Q14.1(B) R14.1
NetQ15_1: Q15.1(B) R15.1
NetQ16_1: Q16.1(B) R16.1
NetQ17_1: Q17.1(B) R17.1
NetQ18_1: Q18.1(B) R18.1
NetQ19_1: Q19.1(B) R19.1
NetQ20_1: Q20.1(B) R20.1
NetQ21_1: Q21.1(B) R21.1
NetQ22_1: Q22.1(B) R22.1
NetQ23_1: Q23.1(B) R23.1
NetQ24_1: Q24.1(B) R24.1
NetQ25_1: Q25.1(B) R25.1
NetQ26_1: Q26.1(B) R26.1
NetQ27_1: Q27.1(B) R27.1
NetQ28_1: Q28.1(B) R28.1
NetQ29_1: Q29.1(B) R29.1
NetQ30_1: Q30.1(B) R30.1
NetQ31_1: Q31.1(B) R31.1
NetQ32_1: Q32.1(B) R32.1
NetQ33_1: Q33.1(B) R33.1
NetQ34_1: Q34.1(B) R34.1
NetQ35_1: Q35.1(B) R35.1
NetQ36_1: Q36.1(B) R36.1
NetQ37_1: Q37.1(B) R37.1
NetQ38_1: Q38.1(B) R38.1
NetQ39_1: Q39.1(B) R39.1
NetQ40_1: Q40.1(B) R40.1
NetQ41_1: Q41.1(B) R41.1
NetQ42_1: Q42.1(B) R42.1
NetQ43_1: Q43.1(B) R43.1
NetQ44_1: Q44.1(B) R44.1
NetQ45_1: Q45.1(B) R45.1
NetQ46_1: Q46.1(B) R46.1
NetQ47_1: Q47.1(B) R47.1
NetQ48_1: Q48.1(B) R48.1
NetQ49_1: Q49.1(B) R49.1
NetQ50_1: Q50.1(B) R50.1
NetQ51_1: Q51.1(B) R51.1
NetQ52_1: Q52.1(B) R52.1
NetQ53_1: Q53.1(B) R53.1
NetQ54_1: Q54.1(B) R54.1
NetQ55_1: Q55.1(B) R55.1
NetQ56_1: Q56.1(B) R56.1
NetQ57_1: Q57.1(B) R57.1
NetQ58_1: Q58.1(B) R58.1
NetQ59_1: Q59.1(B) R59.1
NetQ60_1: Q60.1(B) R60.1
NetQ61_1: Q61.1(B) R61.1
NetQ62_1: Q62.1(B) R62.1
NetQ63_1: Q63.1(B) R63.1
NetQ64_1: Q64.1(B) R64.1
NetQ65_1: Q65.1(B) R65.1
NetQ66_1: Q66.1(B) R66.1
NetQ67_1: Q67.1(B) R67.1
NetQ68_1: Q68.1(B) R68.1
NetQ69_1: Q69.1(B) R69.1
NetQ70_1: Q70.1(B) R70.1
NetQ71_1: Q71.1(B) R71.1
NetQ72_1: Q72.1(B) R72.1
NetQ73_1: Q73.1(B) R73.1
NetQ74_1: Q74.1(B) R74.1
NetQ75_1: Q75.1(B) R75.1
NetQ76_1: Q76.1(B) R76.1
NetQ77_1: Q77.1(B) R77.1
NetQ78_1: Q78.1(B) R78.1
NetQ79_1: Q79.1(B) R79.1
NetQ80_1: Q80.1(B) R80.1
NetQ81_1: Q81.1(B) R81.1
NetQ82_1: Q82.1(B) R82.1
NetQ83_1: Q83.1(B) R83.1
NetQ84_1: Q84.1(B) R84.1
NetQ85_1: Q85.1(B) R85.1
NetQ86_1: Q86.1(B) R86.1
NetQ87_1: Q87.1(B) R87.1
NetQ88_1: Q88.1(B) R88.1
NetQ89_1: Q89.1(B) R89.1
NetQ90_1: Q90.1(B) R90.1
NetQ91_1: Q91.1(B) R91.1
NetQ92_1: Q92.1(B) R92.1
NetQ93_1: Q93.1(B) R93.1
NetQ94_1: Q94.1(B) R94.1
NetQ95_1: Q95.1(B) R95.1
NetQ96_1: Q96.1(B) R96.1
NetQ100_1: Q100.1(B) U1.15(Q0)
NetQ100_2: Q100.2(E) R100.1
NetQ100_3: Q100.3(C) Q101.1(B) R102.2
NetQ101_3: Q101.3(C) R101.1
NetQ200_1: Q200.1(B) U2.5(Q5)
NetQ200_2: Q200.2(E) R200.1
NetQ200_3: Q200.3(C) Q201.1(B) R202.2
NetQ201_3: Q201.3(C) R201.1
NetQ300_1: Q300.1(B) U4.2(Q2)
NetQ300_2: Q300.2(E) R300.1
NetQ300_3: Q300.3(C) Q301.1(B) R302.2
NetQ301_3: Q301.3(C) R301.1
NetQ400_1: Q400.1(B) U5.7(Q7)
NetQ400_2: Q400.2(E) R400.1
NetQ400_3: Q400.3(C) Q401.1(B) R402.2
NetQ401_3: Q401.3(C) R401.1
NetQ500_1: Q500.1(B) U7.4(Q4)
NetQ500_2: Q500.2(E) R500.1
NetQ500_3: Q500.3(C) Q501.1(B) R502.2
NetQ501_3: Q501.3(C) R501.1
NetQ600_1: Q600.1(B) U9.1(Q1)
NetQ600_2: Q600.2(E) R600.1
NetQ600_3: Q600.3(C) Q601.1(B) R602.2
NetQ601_3: Q601.3(C) R601.1
NetQ700_1: Q700.1(B) U10.6(Q6)
NetQ700_2: Q700.2(E) R700.1
NetQ700_3: Q700.3(C) Q701.1(B) R702.2
NetQ701_3: Q701.3(C) R701.1
NetQ800_1: Q800.1(B) U12.3(Q3)
NetQ800_2: Q800.2(E) R800.1
NetQ800_3: Q800.3(C) Q801.1(B) R802.2
NetQ801_3: Q801.3(C) R801.1
NetQP1_1: QP1.1(G) U15.6(OUT)
NetQP1_3: QP1.3(S) RP8.2 RP10.1 RP11.1
NetR1_2: R1.2 U1.1(Q1)
NetR2_2: R2.2 U1.2(Q2)
NetR3_2: R3.2 U1.3(Q3)
NetR4_2: R4.2 U1.4(Q4)
NetR5_2: R5.2 U1.5(Q5)
NetR6_2: R6.2 U1.6(Q6)
NetR7_2: R7.2 U1.7(Q7)
NetR8_2: R8.2 U2.15(Q0)
NetR9_2: R9.2 U2.1(Q1)
NetR10_2: R10.2 U2.2(Q2)
NetR11_2: R11.2 U2.3(Q3)
NetR12_2: R12.2 U2.4(Q4)
NetR13_2: R13.2 U2.6(Q6)
NetR14_2: R14.2 U2.7(Q7)
NetR15_2: R15.2 U3.15(Q0)
NetR16_2: R16.2 U3.1(Q1)
NetR17_2: R17.2 U3.2(Q2)
NetR18_2: R18.2 U3.3(Q3)
NetR19_2: R19.2 U3.4(Q4)
NetR20_2: R20.2 U3.5(Q5)
NetR21_2: R21.2 U3.6(Q6)
NetR22_2: R22.2 U3.7(Q7)
NetR23_2: R23.2 U4.15(Q0)
NetR24_2: R24.2 U4.1(Q1)
NetR25_2: R25.2 U4.3(Q3)
NetR26_2: R26.2 U4.4(Q4)
NetR27_2: R27.2 U4.5(Q5)
NetR28_2: R28.2 U4.6(Q6)
NetR29_2: R29.2 U4.7(Q7)
NetR30_2: R30.2 U5.15(Q0)
NetR31_2: R31.2 U5.1(Q1)
NetR32_2: R32.2 U5.2(Q2)
NetR33_2: R33.2 U5.3(Q3)
NetR34_2: R34.2 U5.4(Q4)
NetR35_2: R35.2 U5.5(Q5)
NetR36_2: R36.2 U5.6(Q6)
NetR37_2: R37.2 U6.15(Q0)
NetR38_2: R38.2 U6.1(Q1)
NetR39_2: R39.2 U6.2(Q2)
NetR40_2: R40.2 U6.3(Q3)
NetR41_2: R41.2 U6.4(Q4)
NetR42_2: R42.2 U6.5(Q5)
NetR43_2: R43.2 U6.6(Q6)
NetR44_2: R44.2 U6.7(Q7)
NetR45_2: R45.2 U7.15(Q0)
NetR46_2: R46.2 U7.1(Q1)
NetR47_2: R47.2 U7.2(Q2)
NetR48_2: R48.2 U7.3(Q3)
NetR49_2: R49.2 U7.5(Q5)
NetR50_2: R50.2 U7.6(Q6)
NetR51_2: R51.2 U7.7(Q7)
NetR52_2: R52.2 U8.15(Q0)
NetR53_2: R53.2 U8.1(Q1)
NetR54_2: R54.2 U8.2(Q2)
NetR55_2: R55.2 U8.3(Q3)
NetR56_2: R56.2 U8.4(Q4)
NetR57_2: R57.2 U8.5(Q5)
NetR58_2: R58.2 U8.6(Q6)
NetR59_2: R59.2 U8.7(Q7)
NetR60_2: R60.2 U9.15(Q0)
NetR61_2: R61.2 U9.2(Q2)
NetR62_2: R62.2 U9.3(Q3)
NetR63_2: R63.2 U9.4(Q4)
NetR64_2: R64.2 U9.5(Q5)
NetR65_2: R65.2 U9.6(Q6)
NetR66_2: R66.2 U9.7(Q7)
NetR67_2: R67.2 U10.15(Q0)
NetR68_2: R68.2 U10.1(Q1)
NetR69_2: R69.2 U10.2(Q2)
NetR70_2: R70.2 U10.3(Q3)
NetR71_2: R71.2 U10.4(Q4)
NetR72_2: R72.2 U10.5(Q5)
NetR73_2: R73.2 U10.7(Q7)
NetR74_2: R74.2 U11.15(Q0)
NetR75_2: R75.2 U11.1(Q1)
NetR76_2: R76.2 U11.2(Q2)
NetR77_2: R77.2 U11.3(Q3)
NetR78_2: R78.2 U11.4(Q4)
NetR79_2: R79.2 U11.5(Q5)
NetR80_2: R80.2 U11.6(Q6)
NetR81_2: R81.2 U11.7(Q7)
NetR82_2: R82.2 U12.15(Q0)
NetR83_2: R83.2 U12.1(Q1)
NetR84_2: R84.2 U12.2(Q2)
NetR85_2: R85.2 U12.4(Q4)
NetR86_2: R86.2 U12.5(Q5)
NetR87_2: R87.2 U12.6(Q6)
NetR88_2: R88.2 U12.7(Q7)
NetR89_2: R89.2 U13.15(Q0)
NetR90_2: R90.2 U13.1(Q1)
NetR91_2: R91.2 U13.2(Q2)
NetR92_2: R92.2 U13.3(Q3)
NetR93_2: R93.2 U13.4(Q4)
NetR94_2: R94.2 U13.5(Q5)
NetR95_2: R95.2 U13.6(Q6)
NetR96_2: R96.2 U13.7(Q7)
NetR109_2: R109.2 U14.44(BOOT0)
NetR110_1: R110.1 U14.20(PB2/BOOT1)
NetU1_9: U1.9(Q7S) U2.14(DS)
NetU2_9: U2.9(Q7S) U3.14(DS)
NetU3_9: U3.9(Q7S) U4.14(DS)
NetU4_9: U4.9(Q7S) U5.14(DS)
NetU5_9: U5.9(Q7S) U6.14(DS)
NetU6_9: U6.9(Q7S) U7.14(DS)
NetU7_9: U7.9(Q7S) U8.14(DS)
NetU8_9: U8.9(Q7S) U9.14(DS)
NetU9_9: U9.9(Q7S) U10.14(DS)
NetU10_9: U10.9(Q7S) U11.14(DS)
NetU11_9: U11.9(Q7S) U12.14(DS)
NetU12_9: U12.9(Q7S) U13.14(DS)

Not connected (* = marked no-connect by the designer): U13 9(Q7S)*

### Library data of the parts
BOOT0 BOOT1 = Header 3: Header, 3-Pin
C1-C13 = CAP: Imported; Manufacturer_Part_Number: 12061A0R5BA12A; Built_By: EMA_UL_Team; Vendor: AVX Corporation; Type: DEV; Value: 100nF
C14-C17 = Cap: Capacitor
C18-C26 = CAP: Imported; Manufacturer_Part_Number: 12061A0R5BA12A; Built_By: EMA_UL_Team; Vendor: AVX Corporation; Type: DEV
CoinCell P1 = Header 2: Header, 2-Pin
CP1-CP3 CP5-CP7 CP9-CP12 CP15 CP16 CP18 = Cap Semi: Capacitor (Semiconductor SIM Model)
D1 = Diode: Default Diode
L1-L3 = Inductor: Code_IEC: 1005
MODULE1 = TINY_STEPDOWN: STEPDOWN MODULE
PROGRAM = Header 6: Header, 6-Pin
Q1-Q96 Q100 Q200 Q300 Q400 Q500 Q600 Q700 Q800 = MMBTA42: Transistor NPN High-Voltage 30V 0.5A
Q101 Q201 Q301 Q401 Q501 Q601 Q701 Q801 = MMBTA92: Transistor PNP High-Voltage -300V -0.5A
QP1 = IRFB4229: Imported; Vendor: Vishay; Built_By: EMA_UL_Team; C: Copyright (C) 2015 Accelerated Designs. All rights reserved
R1-R96 R100-R102 R109-R112 R200-R202 R300-R302 R400-R402 R500-R502 R600-R602 R700-R702 R800-R802 = RES: Resistor
RP2 RP8 RP10-RP12 RP15 RP16 = Res2: Resistor
SW1 SW2 = SW-PB: Switch
U1-U13 = 74HC595D: Imported; Vendor: Nexperia; C: Copyright (C) 2015 Accelerated Designs. All rights reserved
Y1 Y2 = XTAL: Crystal Oscillator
